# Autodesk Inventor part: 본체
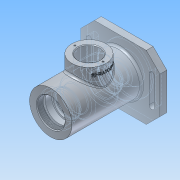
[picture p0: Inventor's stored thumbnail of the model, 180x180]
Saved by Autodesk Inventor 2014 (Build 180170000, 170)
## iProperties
Created: 2017-10
Part Number: 본체
Material: 알루미늄 6061
Document SubType Name: Modeling
Designer: NET
Density: 2.71 g/cm^3
Appearance: 알루미늄 - 평지
Mass: 740.697 g
Surface Area: 652.829 cm^2
Volume: 273.32 cm^3
Author: NET
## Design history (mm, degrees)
sketch "스케치1"
  geometry: L1 (-58, 47)-(58, 47); L2 (58, 47)-(58, -47); L3 (58, -47)-(-58, -47); L4 (-58, -47)-(-58, 47); L5 (-58, 47)-(58, -47); L6 (58, 47)-(-58, -47); 3 further points
  constraints: 12 end point, 3 midpoint, 2 parallel, 1 coincident, 1 horizontal, 1 perpendicular
  dimensions: "d0" = 116 distance of L1.start L1.end; "d1" = 94 distance of L1.end L2.end
extrude "돌출1" new body sketch "스케치1" distance "d2" = 10; taper "d3" = 0 deg
sketch "스케치2"
  geometry: C1 r 31 at (0, 0); 1 further point
  constraints: 1 centre point, 1 coincident
  dimensions: "d4" = 62 diameter of C1
extrude "돌출2" join sketch "스케치2" distance "d5" = 102; taper "d6" = 0 deg
sketch "스케치3"
  geometry: C1 r 35 at (0, 0); 1 further point
  constraints: 1 centre point, 1 coincident
  dimensions: "d7" = 70 diameter of C1
extrude "돌출3" join sketch "스케치3" distance "d8" = 3; taper "d9" = 0 deg
sketch "스케치4"
  geometry: L1 (-35, -3)-(35, -3) reference; L2 (31, 112)-(-31, 112) reference; L3 (0, 112)-(0, -3); L4 (0, 112)-(21, 112); L5 (21, 112)-(21, 103); L6 (0, 103)-(24, 103); L7 (24, 103)-(24, 100); L8 (24, 100)-(20, 100); L9 (20, 100)-(20, 91); L10 (20, 91)-(17.5, 91); L11 (17.5, 91)-(17.5, 87.75); L12 (17.5, 87.75)-(18.5, 87.75); L13 (18.5, 87.75)-(18.5, 86); L14 (18.5, 86)-(17.5, 86); L15 (17.5, 86)-(17.5, 75); L16 (17.5, 75)-(26, 75); L17 (26, 75)-(26, 37); L18 (26, 37)-(17.5, 37); L19 (17.5, 37)-(17.5, 26); L20 (17.5, 26)-(16.5, 26); L21 (16.5, 26)-(16.5, 21); L22 (16.5, 21)-(10, 21); L23 (10, 21)-(10, 18.3); L24 (10, 18.3)-(12.5, 18.3); L25 (12.5, 18.3)-(12.5, 11); L26 (0, -3)-(22, -3); L27 (12.5, 11)-(16, 11); L28 (16, 11)-(22, -3); 2 further points
  constraints: 52 end point, 18 parallel, 5 point on line, 4 perpendicular, 3 collinear, 2 midpoint
  dimensions: "d40" = 42 diameter of L5 L3; "d41" = 48 diameter of L7 L3; "d42" = 40 diameter of L9 L3; "d43" = 35 diameter of L11 L3; "d44" = 37 diameter of L13 L3; "d45" = 52 diameter of L17 L3; "d46" = 33 diameter of L21 L3; "d47" = 20 diameter of L23 L3; "d48" = 25 diameter of L25 L3; "d50" = 7.3 distance of L24.end L25.end; "d51" = 2.7 distance of L22.end L23.end; "d52" = 5 distance of L20.end L21.end; "d53" = 11 distance of L18.end L19.end; "d54" = 38 distance of L16.end L17.end; "d55" = 1.75 distance of L12.end L13.end; "d56" = 3.25 distance of L10.end L11.end; "d57" = 9 distance of L8.end L9.end; "d58" = 3 distance of L6.end L7.end; "d62" = 44 diameter of L26.end L3; "d63" = 32 diameter of L27.end L3; "d64" = 14 distance between parallel lines of L1 L27
hole "구멍1" diameter "d12" = 40.376; stored, may be unused: countersink angle "d16" = 90 deg, drill point angle "d18" = 0 deg; dims "d13" = 6, "d14" = 4, "d15" = 2, "d17" = 9, "d60" = 10, "d61" = 10
revolve "회전1" stored, may be unused: angle "d59" = 90 deg
node "작업 평면1"
sketch "스케치5"
  geometry: L1 (31, 112)-(-31, 112) reference; C1 r 25 at (0, 56); 2 further points
  constraints: 1 centre point, 1 midpoint, 1 vertical alignment
  dimensions: "d66" = 56 distance from line of L1 C1.centre; "d67" = 50 diameter of C1
extrude "돌출4" join sketch "스케치5" stored distance "d68" = 9; taper "d69" = 0 deg
hole "구멍2" diameter "d72" = 32; stored, may be unused: countersink angle "d76" = 90 deg, drill point angle "d78" = 0 deg; dims "d70" = 10, "d71" = 10, "d73" = 6, "d74" = 4, "d75" = 2, "d77" = 47
chamfer "모따기1" distance "d79" = 20; stored, may be unused: second distance "d80" = 2, angle "d81" = 45 deg
sketch "스케치6"
  geometry: L1 (58, -27)-(58, 27) reference; L2 (-38, -47)-(38, -47) reference; L3 (46, 20)-(46, -20); L4 (42, 20)-(42, -20); L5 (50, -20)-(50, 20); C1 r 35 at (0, 0) reference; A1 r 4 centre (46, 20) between (50, 20) and (42, 20); A2 r 4 centre (46, -20) between (42, -20) and (50, -20); 3 further points
  constraints: 8 end point, 4 point on circle, 4 tangent, 3 midpoint, 2 centre point, 1 horizontal alignment, 1 parallel, 1 perpendicular
  dimensions: "d82" = 4 radius of A1; "d83" = 46 horizontal distance of L3.end C1.centre; "d84" = 40 distance of L5.start L5.end
extrude "돌출5" cut sketch "스케치6" stored distance "d85" = 9; taper "d86" = 0 deg
sketch "스케치7"
  geometry: C1 r 16 at (0, 0) reference; 3 further points
  constraints: 2 horizontal alignment
  dimensions: "d87" = 20.5 distance of C1.centre point (-20.5, 0); "d88" = 20.5 distance of C1.centre point (20.5, 0)
hole "구멍3" sketch "스케치7" at (-20.5, 0), (20.5, 0) diameter "d89" = 2.459; stored, may be unused: countersink angle "d93" = 90 deg, drill point angle "d95" = 118 deg; dims "d90" = 6, "d91" = 4, "d92" = 2, "d94" = 8
node "작업 평면2"
sketch "스케치8"
  geometry: L1 (0, 25)-(0, -25) reference; L2 (-16, 56)-(-78, 56) reference; 2 further points
  constraints: 1 other
  dimensions: "d96" = 10 distance from line of L1 point (-10, 0); "d97" = 56 distance from line of L2 point (-10, 0)
feature "엠보싱1" sketch "스케치8" dims "d0" = 116, "d1" = 94, "d98" = 0.5, "d99" = 0
chamfer "모따기2" distance "d100" = 1; stored, may be unused: second distance "d101" = 2, angle "d102" = 45 deg
chamfer "모따기3" distance "d103" = 1; stored, may be unused: second distance "d104" = 2, angle "d105" = 45 deg
chamfer "모따기4" distance "d106" = 0.7; stored, may be unused: second distance "d107" = 2, angle "d108" = 30 deg
chamfer "모따기5" distance "d109" = 1; stored, may be unused: second distance "d110" = 2, angle "d111" = 45 deg
chamfer "모따기6" distance "d112" = 1; stored, may be unused: second distance "d113" = 2, angle "d114" = 45 deg
fillet "모깎기1" dims "d115" = 0.3
fillet "모깎기2" dims "d116" = 3
fillet "모깎기3" dims "d117" = 3
fillet "모깎기4" dims "d118" = 3
fillet "모깎기5" dims "d119" = 0.3
node "솔리드1"
mirror "대칭1"
other parameters: "d65" = 47
